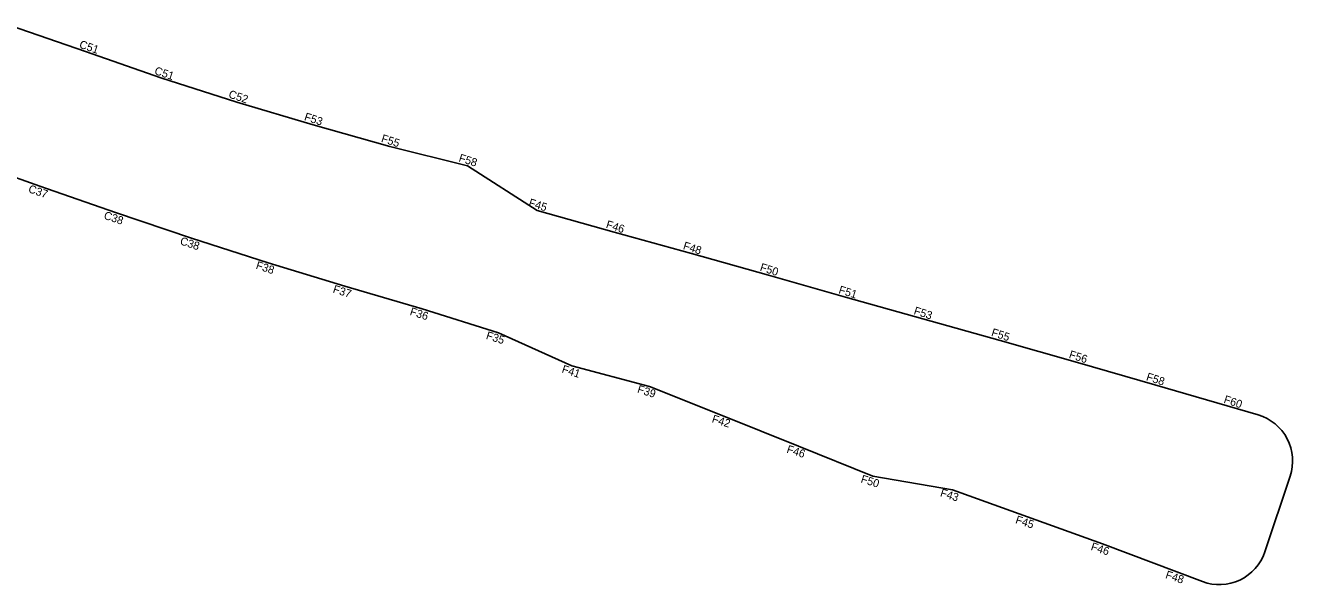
# Model space of a CAD drawing. Extents: x 2164037 to 2171931, y 206073 to 210167.
# Drawn here: x 2166391 to 2167182, y 208925 to 209274 of the extents above; entities that cross this region are included whole.
import ezdxf

# ---------------------------------------------------------------- set-up
doc = ezdxf.new("R2010")
doc.units = 0
doc.layers.add('RD_PD_CstnLmt', color=7, linetype='Continuous')
doc.layers.add('RD_PD_TX_CstnLmt', color=7, linetype='Continuous')

msp = doc.modelspace()

# ---------------------------------------------------------------- linework, layer by layer
at = {"layer": 'RD_PD_CstnLmt'}
for p, q in [((2166381.15, 209274.21), (2166428.15, 209257.81)), ((2166428.15, 209257.81), (2166475.14, 209241.34)), ((2166475.14, 209241.34), (2166522.62, 209226.35)), ((2166522.62, 209226.35), (2166570.35, 209212.11)), ((2166570.35, 209212.11), (2166618.3, 209198.61)), ((2166618.3, 209198.61), (2166666.67, 209186.48)), ((2166352.3, 209190.7), (2166399.55, 209173.89)), ((2166666.67, 209186.48), (2166710.24, 209158.6)), ((2166399.55, 209173.89), (2166446.89, 209157.29)), ((2166446.89, 209157.29), (2166494.45, 209141.35)), ((2166710.24, 209158.6), (2166758.4, 209145.05)), ((2166758.4, 209145.05), (2166806.62, 209131.71)), ((2166494.45, 209141.35), (2166542.21, 209126.03)), ((2166542.21, 209126.03), (2166590.15, 209111.27)), ((2166806.62, 209131.71), (2166854.8, 209118.22)), ((2166854.8, 209118.22), (2166902.89, 209104.48)), ((2166590.15, 209111.27), (2166638.32, 209097.25)), ((2166902.89, 209104.48), (2166951.07, 209091)), ((2166638.32, 209097.25), (2166686.04, 209082.26)), ((2166951.07, 209091), (2166999.36, 209077.51)), ((2166686.04, 209082.26), (2166731.97, 209061.69)), ((2166999.36, 209077.51), (2167047.71, 209063.78)), ((2167047.71, 209063.78), (2167096, 209049.82)), ((2166731.97, 209061.69), (2166780.33, 209048.78)), ((2166780.33, 209048.78), (2166826.9, 209030.23)), ((2167096, 209049.82), (2167160.51, 209030.97)), ((2166826.9, 209030.23), (2166873.38, 209011.37)), ((2166873.38, 209011.37), (2166919.92, 208992.71)), ((2166919.92, 208992.71), (2166969.55, 208984.09)), ((2167164.78, 208945.48), (2167180.55, 208992.67)), ((2166969.55, 208984.09), (2167016.45, 208967.23)), ((2167016.45, 208967.23), (2167063.4, 208950.52)), ((2167063.4, 208950.52), (2167125.7, 208926.93))]:
    msp.add_line(p, q, dxfattribs=at)
for centre, start, end in [((2167152.1, 209002.18), 341.52278, 73.71709), ((2167136.33, 208954.98), 249.2606, 341.52278)]:
    msp.add_arc(centre, 30, start, end, dxfattribs=at)

# ---------------------------------------------------------------- texts
at = {"layer": 'RD_PD_TX_CstnLmt'}
for s, rotation, p in [('C51', 341.18108, (2166423.84, 209260.34)), ('C51', 341.41981, (2166470.81, 209243.85)), ('C52', 341.65854, (2166517.09, 209229.24)), ('F53', 341.89727, (2166564.39, 209215.11)), ('F55', 342.13601, (2166612.44, 209201.55)), ('F58', 342.37474, (2166660.89, 209189.36)), ('C37', 341.18108, (2166392.01, 209170.12)), ('F45', 342.41105, (2166704.52, 209161.46)), ('C38', 341.41981, (2166439.19, 209153.55)), ('F46', 342.41105, (2166752.83, 209147.87)), ('C38', 341.65854, (2166486.76, 209137.58)), ('F48', 342.41105, (2166800.99, 209134.54)), ('F38', 341.89727, (2166534.17, 209122.35)), ('F50', 342.41105, (2166849, 209121.11)), ('F37', 342.13601, (2166582.29, 209107.5)), ('F51', 342.41105, (2166898.15, 209107.03)), ('F36', 342.37474, (2166630.36, 209093.48)), ('F53', 342.41105, (2166945.09, 209093.95)), ('F35', 342.41105, (2166677.94, 209078.53)), ('F55', 342.30105, (2166993.49, 209080.43)), ('F56', 342.06231, (2167042, 209066.68)), ('F41', 342.41105, (2166725.26, 209057.52)), ('F58', 341.82358, (2167090.25, 209052.76)), ('F39', 342.41105, (2166772.38, 209045)), ('F60', 341.58485, (2167138.65, 209038.64)), ('F42', 342.41105, (2166818.99, 209026.44)), ('F46', 342.41105, (2166865.69, 209007.51)), ('F50', 342.41105, (2166912, 208988.93)), ('F43', 342.30105, (2166961.59, 208980.33)), ('F45', 342.06231, (2167008.59, 208963.47)), ('F46', 341.82358, (2167055.67, 208946.74)), ('F48', 341.58485, (2167102.22, 208929.14))]:
    msp.add_text(s, height=5, rotation=rotation, dxfattribs=at).set_placement(p)

doc.saveas('drawing.dxf')
